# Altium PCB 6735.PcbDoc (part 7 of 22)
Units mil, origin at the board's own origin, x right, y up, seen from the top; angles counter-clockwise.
Board outline 2641.73 x 5165.35 mil, 6 copper layers (Top, Inner Layer 2, Inner Layer 3, Inner Layer 4, Inner Layer 5, Bottom), stack 35.7 mil thick; 1011 components, 790 nets, 4118 pads, 9325 vias.
Unrouted connection lines stored in the file: 4610.
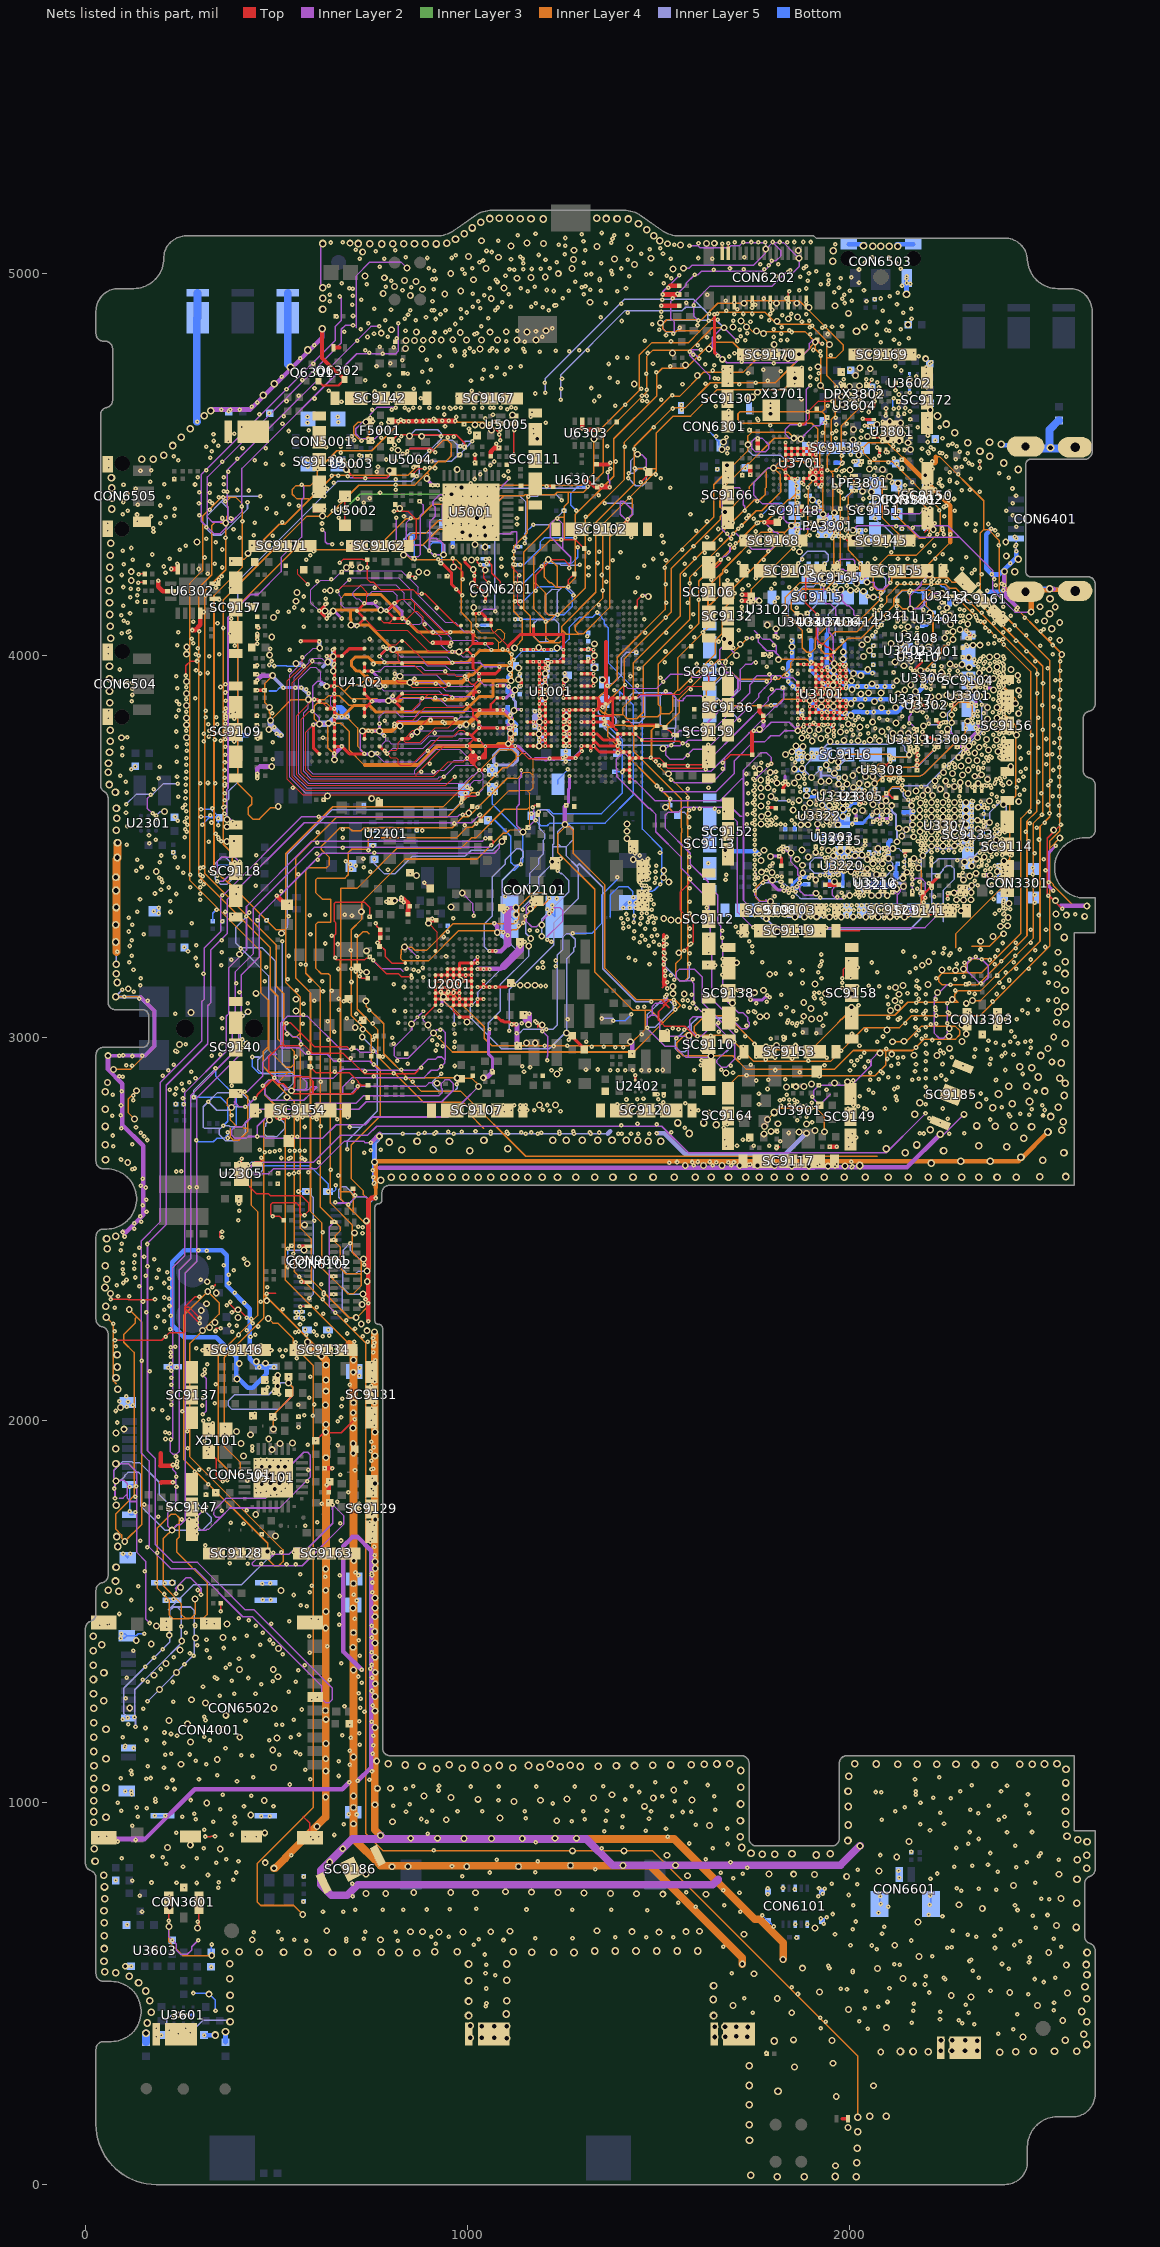
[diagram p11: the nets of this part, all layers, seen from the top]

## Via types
v1: diameter 12, hole 4, Top to Inner Layer 2, 3329 vias
v2: diameter 12, hole 4, Inner Layer 5 to Bottom, 3071 vias
v3: diameter 18, hole 10, Inner Layer 2 to Inner Layer 5, 1928 vias
v4: diameter 10, hole 4, Top to Inner Layer 2, 525 vias
v5: diameter 20, hole 12, Top to Bottom, 472 vias

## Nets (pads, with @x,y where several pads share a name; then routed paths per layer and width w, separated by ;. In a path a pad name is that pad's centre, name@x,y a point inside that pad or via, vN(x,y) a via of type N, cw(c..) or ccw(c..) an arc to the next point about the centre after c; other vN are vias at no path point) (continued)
D_GND: (continued)
  Top w4: DPX3802.5@2044.35,4707.8 DPX3802.5@2045.14,4707.8 ; DPX3802.5@2044.35,4707.8 DPX3802.5@2044.35,4709.22 ; DPX3802.5@2044.35,4709.22 2044.96,4708.14 DPX3802.5@2045.14,4707.8 ; DPX3802.5@2044.35,4709.22 v1(2043.31,4711.09) 2044.35,4710.05 DPX3802.5@2044.35,4709.22 ; U3308.2@2082.58,3700.59 U3308.7@2105.57,3723.58 ; U3801.4@2094.55,4633.33 v1@2094.55,4641.85 ; U3801.4@2094.55,4633.33 v1@2094.55,4641.85 ; DIPX3801.2@2125.6,4406.79 DIPX3801.2@2125.6,4406.09 DIPX3801.2@2125.6,4406.79 ; U3801.2@2126.8,4633.33 U3801.2@2126.05,4633.33 U3801.2@2126.8,4633.33 ; v1(2141.8,4633.33) 2141.67,4633.46 v1(2141.8,4633.33) ; U3801.15@2142.34,4538.84 U3801.15@2141.8,4538.85 U3801.15@2142.34,4538.84 ; U3801.17@2157.54,4570.83 2157.54,4570.34 U3801.17@2157.54,4570.83 ; U3801.20@2157.54,4618.33 U3801.20@2157.55,4617.59 U3801.20@2157.54,4618.33 ; DIPX3801.4@2159.06,4431.83 DIPX3801.4@2159.07,4431.68 DIPX3801.4@2159.06,4431.83 ; SC9150.3@2202.95,4330.72 SC9150.3@2202.59,4358.85 SC9150.3@2202.95,4330.72 ; v1@205.32,1545.49 205.89,1544.92 205.95,1544.86 v1(205.95,1544.99) 205.44,1545.49 v1@205.32,1545.49 ; C4115.2@465.61,3909.49 v1(465.95,3909.83) 468.61,3909.83 C4115.2@468.95,3909.49 C4115.2@465.61,3909.49 ; U5003.2@684.76,4502.42 v1(684.95,4502.23) U5003.2@684.76,4502.42 ; U5003.5@707.4,4502.42 v1(707.47,4502.49) U5003.5@707.4,4502.42 ; U4102.W13@828.35,3782.47 828.53,3782.65 U4102.W13@828.35,3782.47 ; v4(1029.98,3732.26) 1031.08,3732.11 1030.13,3732.11 v4(1029.98,3732.26) ; U1001.E3@1045.3,3700.34 v4(1045.72,3700.77) 1045.77,3700.69 U1001.E3@1045.3,3700.34 ; U5005.3@1120.26,4626.79 U5005.3@1121.31,4626.8 U5005.3@1120.26,4626.79 ; U2402.C2@1438.44,2889.84 1438.44,2891.96 U2402.C2@1438.44,2889.84 ; U3701.C4@1908.3,4526.9 1909.49,4526.9 1910.68,4526.9 v4(1910.68,4526.71) U3701.C4@1908.3,4526.9 ; LPF3801.3@2010.58,4431.4 v1(2011.31,4432.09) LPF3801.3@2010.58,4431.4 ; U3801.14@2126.05,4538.84 v1(2126.31,4539.09) U3801.14@2126.05,4538.85
  Top w5: U1001.C6@1011.72,3745.5 1014.23,3742.99 1019.73,3737.49 ; U1001.C6@1014.23,3748.01 1013.96,3747.74 1014.23,3747.47 1019.73,3741.97 ; 1019.73,3737.49 1019.73,3741.97 ; 1019.73,3737.49 1027,3730.22 1027.47,3729.75 v4(1029.98,3732.26) 1029.71,3732 1019.74,3741.97
  Top w6: Q6301.2@609.7,4717.85 620.56,4706.99 662.33,4706.99 677.2,4721.87 Q6302.2@677.2,4722.85 ; v4(998.48,3732.26) 1002.11,3735.89 1004.08,3737.86 ; 1010.36,3789.83 1010.36,3791.38 v4(1029.98,3811) ; U1001.C6@1013.96,3747.74 1011.72,3745.5 1008.74,3742.52 ; v4(1014.23,3999.98) U1001.B23@998.48,4015.73 ; 1014.62,3858.11 1014.08,3857.57 1014.08,3842.64 U1001.D11@1029.98,3826.75 ; 1017.36,3782.83 998.48,3763.95 v4(998.48,3763.76) ; 1018.96,3723.88 1018.89,3723.88 1013.84,3728.92 1013.28,3729.49 1012.72,3730.05 1006.88,3735.89 ; 1025.29,3730.22 1021.04,3730.22 1014.23,3737.03 1008.74,3742.52 ; 1060.74,3859.23 1060.74,3873.26 ; U1001.AC12@1329.19,3842.5 1379.56,3842.49 ; 1390.46,3804.49 1379.56,3815.39 1379.56,3842.49 ; U1001.AG15@1392.18,3889.74 1379.56,3889.74 1379.56,3842.49 ; v1(1438.31,2902.09) 1438.14,2901.92 1438.14,2889.54 U2402.C2@1438.44,2889.84 ; U3101.L11@1863.66,3851.35 U3101.L10@1863.66,3867.09 ; v4(1879.41,3819.85) v4(1895.16,3819.85) ; v1(1950.65,3622.59) 1962.26,3622.59 U3323.1@1962.78,3623.11 ; U3305.10@2012.15,3630.59 v1(2051.13,3630.59) ; U3305.2@2022.98,3613.86 U3305.3@2038.33,3613.86 ; v1(2095.65,3640.59) 2098.65,3640.59 2110.65,3628.59 L3342.2@2120.65,3628.59 ; U3306.7@2167.06,3960.28 2167.06,3962.16 2167.15,3962.16 2183.48,3978.49 2183.7,3978.49 2188.13,3982.92 U3410.1@2188.13,3987.72 ; v1(2193.65,3354.59) 2193.65,3366.48 2193.65,3377.27 2207.98,3391.59 v1(2214.65,3391.59) ; v4(998.48,3763.76) U1001.C6@1014.23,3748.01 ; v4(998.48,3763.76) U1001.C6@1014.23,3748.01 ; U1001.B23@998.48,4015.73 v4(1014.23,3999.98) U1001.B23@998.48,4015.73 ; 1004.08,3737.86 1004.91,3737.86 1006.88,3735.89 ; 1004.08,3737.86 1005.06,3738.84 ; 1005.06,3738.84 1006.88,3737.01 1006.88,3735.89 ; 1005.06,3738.84 1008.74,3742.52 ; 1008.74,3742.52 U1001.C6@1014.23,3748.01 ; 1060.74,3873.26 U1001.G15@1077.22,3889.74 1060.74,3873.26
  Top w7: v4(1863.66,3835.6) v4(1879.41,3835.6) U3101.J12@1895.16,3835.6 U3101.J11@1895.16,3851.35 ; U3101.L10@1863.66,3867.09 v4(1863.66,3882.84) ; v4(1863.66,3914.34) v4(1863.66,3898.59) ; U3101.L3@1863.66,3977.33 v4(1879.41,3977.33) ; U3101.K8@1879.41,3898.59 v4(1863.66,3898.59) ; v4(1895.16,3819.85) v4(1910.9,3819.85) v4(1926.65,3819.85) v4(1942.4,3819.85) v4(1958.15,3819.85) v4(1958.15,3804.1) v4(1958.15,3788.35) ; v4(1895.16,3898.59) U3101.J9@1895.16,3882.84 ; U3101.J4@1895.16,3961.58 U3101.H4@1910.9,3961.58 ; v4(1895.16,3977.33) U3101.H3@1910.9,3977.33 U3101.G3@1926.65,3977.33 v4(1926.65,3961.58) ; v4(1910.9,3867.09) U3101.H11@1910.9,3851.35 ; v4(1910.9,3898.59) v4(1910.9,3882.84) ; U3101.H6@1910.9,3930.09 U3101.G6@1926.65,3930.09 v4(1942.4,3930.09) ; U3101.G9@1926.65,3882.84 v4(1910.9,3882.84) ; U3101.G7@1926.65,3914.34 v4(1942.4,3914.34) ; U3101.G2@1926.65,3993.08 U3101.F2@1942.4,3993.08 ; v4(1942.4,3898.59) v4(1942.4,3882.84) U3101.E9@1958.15,3882.84 ; U3101.E10@1958.15,3867.09 U3101.E9@1958.15,3882.84 ; U3101.E6@1958.15,3930.09 v4(1942.4,3930.09) ; U3101.C11@1988.18,3851.35 U3101.D11@1973.9,3851.35 ; v4(1989.64,3835.6) U3101.D12@1973.9,3835.6 ; v4(1989.64,3851.35) v4(1989.64,3867.09) ; v4(1863.66,3882.84) v4(1863.66,3898.59) ; v4(1863.66,3882.84) v4(1879.41,3882.84) U3101.J9@1895.16,3882.84 ; U3101.J11@1895.16,3851.35 v4(1895.16,3867.09) U3101.J9@1895.16,3882.84 ; U3101.J11@1895.16,3851.35 U3101.H11@1910.9,3851.35 ; U3101.J9@1895.16,3882.84 v4(1910.9,3882.84) ; U3101.H11@1910.9,3851.35 v4(1926.65,3851.35) ; U3101.H4@1910.9,3961.58 U3101.H5@1910.9,3945.83 U3101.G5@1926.65,3945.83 ; U3101.H4@1910.9,3961.58 v4(1926.65,3961.58) ; v4(1926.65,3851.35) v4(1942.4,3851.35) ; v4(1926.65,3851.35) U3101.G10@1926.65,3867.09 v4(1942.4,3867.09) v4(1942.4,3851.35) ; U3101.G5@1926.65,3945.83 v4(1926.65,3961.58) ; U3101.G5@1926.65,3945.83 v4(1942.4,3945.83) v4(1942.4,3961.58) ; v4(1926.65,3961.58) v4(1942.4,3961.58) ; v4(1942.4,3851.35) v4(1942.4,3835.6) U3101.E12@1958.15,3835.6 ; v4(1942.4,3851.35) v4(1958.15,3851.35) ; v4(1942.4,3914.34) v4(1942.4,3930.09) ; v4(1942.4,3914.34) U3101.E7@1958.15,3914.34 ; v4(1942.4,3961.58) U3101.E4@1958.15,3961.58 ; U3101.E12@1958.15,3835.6 v4(1958.15,3851.35) ; U3101.E12@1958.15,3835.6 U3101.D12@1973.9,3835.6 ; v4(1958.15,3851.35) U3101.D11@1973.9,3851.35 ; U3101.E9@1958.15,3882.84 U3101.E8@1958.15,3898.59 ; U3101.E8@1958.15,3898.59 U3101.D8@1973.9,3898.59 ; U3101.E8@1958.15,3898.59 U3101.E7@1958.15,3914.34 ; U3101.E7@1958.15,3914.34 v4(1973.9,3914.34) ; U3101.E4@1958.15,3961.58 U3101.E3@1958.15,3977.33 v4(1973.9,3977.33) ; U3101.E4@1958.15,3961.58 v4(1973.9,3961.58) ; U3101.D12@1973.9,3835.6 U3101.D11@1973.9,3851.35 ; U3101.D11@1973.9,3851.35 U3101.D10@1973.9,3867.09 ; U3101.D10@1973.9,3867.09 U3101.D9@1973.9,3882.84 ; U3101.D10@1973.9,3867.09 v4(1989.64,3867.09) ; U3101.D9@1973.9,3882.84 U3101.D8@1973.9,3898.59 ; U3101.D9@1973.9,3882.84 v4(1989.64,3882.84) v4(1989.64,3867.09) ; U3101.D8@1973.9,3898.59 v4(1973.9,3914.34) ; v4(1973.9,3914.34) v4(1989.64,3914.34) v4(1989.64,3930.09) ; v4(1973.9,3914.34) v4(1973.9,3930.09) ; v4(1973.9,3930.09) v4(1989.64,3930.09) ; v4(1973.9,3930.09) v4(1973.9,3945.83) v4(1989.64,3945.83) ; v4(1973.9,3961.58) v4(1989.64,3961.58) ; v4(1973.9,3961.58) v4(1973.9,3977.33) ; v4(1973.9,3977.33) v4(1989.64,3977.33) v4(1989.64,3961.58) ; v4(1989.64,3930.09) v4(1989.64,3945.83) ; v4(1989.64,3945.83) v4(1989.64,3961.58)
  Top w8: v1(559.31,2424.09) v1@559.67,2423.73 ; v1(559.31,2455.09) v1@559.46,2455.23 ; v1(562.95,4037.49) v1@563.84,4038.37 ; v1(564.31,2362.09) v1@565.66,2360.74 ; v1(596.08,3819.11) 596.08,3758.83 U4102.AA2@611.82,3743.1 ; v1(598.95,3885.49) 607.6,3885.11 ; U4102.R3@631.5,3861.21 v1(651.18,3861.21) ; U4102.M3@631.5,3920.27 v1(651.18,3920.26) ; v1(631.5,4097.43) v1(611.81,4117.11) U4102.A3@631.5,4136.8 ; v1(651.18,3743.1) U4102.W4@651.19,3782.47 v1(651.18,3821.84) v1(651.18,3841.52) v1(651.18,3861.21) ; U4102.Y4@651.19,3762.79 v1(670.87,3762.78) 690.55,3743.1 v1(729.92,3743.1) ; U4102.G4@651.19,4018.69 U4102.H4@651.19,3999.01 ; U4102.B7@710.24,4117.12 v1(729.92,4136.8) U4102.B7@710.24,4117.12 ; U4102.W8@729.93,3782.47 U4102.V8@729.93,3802.16 v1(749.61,3802.15) ; U4102.T8@729.93,3841.53 U4102.R8@729.93,3861.21 v1(749.61,3880.89) U4102.N8@729.93,3900.58 U4102.M8@729.93,3920.27 ; U4102.J8@729.93,3979.32 U4102.K8@729.93,3959.64 v1(749.61,3959.63) ; U4102.G8@729.93,4018.69 729.45,4018.22 690.08,4018.22 U4102.H5@670.87,3999.01 U4102.H4@651.19,3999.01 ; U4102.Y10@769.3,3762.79 v1(788.98,3743.1) ; v1(769.29,3999) v1(788.98,4018.69) ; U4102.B11@788.98,4117.12 v1(808.66,4136.8) U4102.B11@788.98,4117.12 ; U4102.A12@810.9,4136.8 815.01,4140.91 816.01,4141.91 ; U4102.R13@828.35,3861.21 v1(808.66,3880.89) ; v1(828.35,4097.43) U4102.C12@808.67,4097.43 ; U4102.W13@828.53,3782.65 837.58,3782.65 845.63,3782.65 v1(854.08,3791.11) ; U2001.L12@915.58,3085.71 U2001.L11@915.58,3101.46 ; v1(930.95,4241.83) 932.92,4241.83 957.58,4217.17 957.58,4186.81 v1(986.3,4158.09) ; U2001.G10@978.38,3117.15 U2001.G10@978.31,3117.09 ; U2001.G14@978.57,3054.22 v4(1010.07,3054.22) ; 987.95,3164.49 v4(994.95,3164.49) v4(994.95,3164.49) ; v1(993.08,4254.11) 993.08,4244.11 1018.3,4218.89 1018.3,4189.11 1046.08,4161.33 U1001.E31@1046.08,4142.07 ; U1001.B9@998.48,3795.25 1004.94,3795.25 1010.36,3789.83 1017.36,3782.83 1021.08,3779.11 U1001.D8@1029.98,3779.11 ; U1001.B5@1002.31,3730.14 1002.31,3731.31 1003.25,3732.26 1006.88,3735.89 ; 1009.76,3720.98 1013.84,3716.89 1013.84,3718.77 1018.96,3723.88 1025.29,3730.22 1027,3730.22 1027.93,3730.22 1029.71,3732 v4(1029.98,3732.26) ; U1001.C15@1014.23,3889.74 1014.7,3890.21 1014.7,3900.73 1019.46,3905.48 v4(1029.98,3905.48) ; 1014.23,3968.48 v4(1014.23,3999.98) ; v4(1014.23,4062.97) 1014.23,4031.47 v4(1045.72,4031.47) ; 1014.62,3858.11 v4(1031.08,3858.11) 1048.08,3858.11 1048.22,3858.24 v4(1092.97,3858.25) ; v1(1019.08,4525.49) 1019.08,4515.36 L5010.2@1019.08,4505.83 ; U2001.D12@1025.82,3085.71 v4(1025.82,3101.46) v4(1041.57,3101.46) ; v4(1025.82,3132.96) v4(1041.57,3132.96) ; v4(1025.82,3180.2) v4(1041.57,3180.2) v4(1057.32,3180.2) ; v4(1025.82,3211.7) v4(1025.82,3195.95) U2001.E5@1010.07,3195.95 ; v4(1029.98,3700.77) v4(1045.72,3700.77) ; v4(1029.98,3952.73) v4(1029.98,3936.99) ; v4(1029.98,3779.51) U1001.D8@1029.98,3779.11 ; v4(1029.98,3811) U1001.H10@1092.97,3811 1093.07,3811.11 v4(1107.08,3811.11) 1110.95,3807.24 1110.95,3796.49 ; v4(1029.98,3952.73) 1055.91,3952.73 1056.01,3952.83 1072.95,3952.83 1082.95,3962.83 v4(1082.95,3970.49) ; v4(1041.57,3148.7) v4(1041.57,3132.96) ; v4(1045.72,4141.71) U1001.E31@1046.08,4142.07 ; v4(1045.72,4031.47) 1046.09,4031.83 1064.95,4031.83 ; U1001.E31@1046.08,4142.06 1045.76,4141.75 U1001.E31@1046.08,4142.07 ; v4(1057.32,3227.44) v4(1073.06,3227.44) ; U1001.F27@1061.47,4078.72 U1001.F28@1061.47,4094.47 U1001.E28@1045.72,4094.47 1046.08,4094.81 1046.08,4102.1 1037.98,4110.21 v4(1029.98,4110.21) ; U2001.A14@1073.06,3054.22 1078.15,3054.22 1082.73,3049.63 1082.73,3049.49 1087.39,3044.83 1091.71,3044.83 1094.71,3041.83 1108.95,3041.83 v1(1114.95,3035.83) ; U1001.G15@1077.22,3889.74 U1001.H15@1092.97,3889.74 ; U1001.G17@1077.22,3921.24 U1001.H17@1092.97,3921.24 ; v4(1104.95,4015.49) 1104.95,4023.07 1137.36,4055.49 1171.71,4055.49 ; C2011.2@1112.95,3143.83 1109.66,3140.54 1102.08,3132.96 v4(1073.06,3132.96) v4(1057.32,3132.96) v4(1041.57,3132.96) ; U1001.K9@1124.46,3795.25 1112.19,3795.25 1110.95,3796.49 ; v4(1140.21,3921.24) U1001.L18@1140.21,3936.99 ; v4(1140.21,4015.73) 1148.95,4015.72 ; U1001.M7@1155.96,3763.76 U1001.N7@1171.71,3763.76 U1001.P7@1187.46,3763.76 ; U1001.M9@1155.96,3795.25 U1001.N9@1171.71,3795.25 U1001.P9@1187.46,3795.25 ; U1001.M11@1155.96,3826.75 v4(1171.71,3826.75) U1001.P11@1187.46,3826.75 ; U1001.M21@1155.96,3984.23 v4(1171.71,3984.23) ; U1001.N27@1171.71,4078.72 1171.71,4055.49 ; 1209.02,4015.73 v4(1199.95,4015.73) 1182.95,4015.73 v4(1171.71,4015.73) 1161.78,4015.72 U1001.M23@1155.96,4015.73 ; 1209.03,4015.72 v4(1218.95,4015.73) ; v4(1214.29,3730.78) 1215.93,3732.42 v4(1249.04,3732.42) 1255.09,3732.42 1255.34,3732.17 v4(1282.48,3732.17) 1282.48,3734.02 v4(1298.95,3750.49) 1297.69,3750.84 v4(1297.69,3763.76) v4(1329.19,3763.76) ; U1001.T7@1218.95,3763.76 v4(1203.2,3763.76) ; U1001.V18@1250.45,3936.99 v4(1250.45,3921.24) U1001.V16@1250.45,3905.49 1250.45,3889.74 U1001.W15@1266.2,3889.74 U1001.Y15@1281.94,3889.74 U1001.AA15@1297.69,3889.74 U1001.AB15@1313.44,3889.74 U1001.AC15@1329.19,3889.74 1338.7,3889.74 1341.95,3886.49 1343.95,3879.49 ; C2055.2@1273.95,3005.49 1273.95,3005.09 1273.95,3002.99 1291.95,2984.99 1292.01,2984.99 1304.95,2972.05 C2058.2@1304.95,2969.49 ; v4(1297.69,3795.25) v4(1329.19,3795.25) ; v4(1297.69,3826.75) v4(1329.19,3826.75) ; U1001.AA17@1297.69,3921.24 U1001.AB17@1313.44,3921.24 v4(1329.19,3921.24) v4(1329.19,3952.73) U1001.AB19@1313.44,3952.73 U1001.AA19@1297.69,3952.73 ; U1001.AA21@1297.69,3984.23 U1001.AB21@1313.44,3984.23 v4(1329.19,3984.23) v4(1329.19,4015.73) U1001.AB23@1313.44,4015.73 U1001.AA23@1297.69,4015.73 ; U6301.B1@1302.7,4458.49 1313.95,4458.49 1330.95,4441.49 C6303.2@1338.95,4441.49 ; v4(1321.95,3751.49) 1321.95,3756.52 ; 1368.2,3826.75 v4(1329.19,3826.75) ; U1001.AH3@1407.93,3700.77 U1001.AJ3@1423.68,3700.77 ; U1001.AJ1@1423.68,3669.27 U1001.AJ2@1423.68,3685.02 U1001.AJ3@1423.68,3700.77 ; U1001.AK9@1439.43,3795.25 U1001.AJ9@1423.68,3795.25 U1001.AH9@1407.93,3795.25 U1001.AG9@1392.18,3795.25 U1001.AG8@1392.18,3779.51 ; U1001.AK15@1439.42,3889.74 v4(1423.68,3889.74) U1001.AH15@1407.93,3889.74 U1001.AG15@1392.18,3889.74 1376.43,3889.74 U1001.AE14@1360.69,3873.99 1347.45,3873.99 ; U1001.AL5@1455.17,3732.26 U1001.AK5@1439.43,3732.26 U1001.AJ5@1423.68,3732.26 ; 1512.95,3270.86 v1(1512.95,3255.11) v1(1512.95,3239.36) v1(1512.95,3223.62) v1(1512.95,3207.87) v1(1512.95,3192.12) 1512.95,3143.45 1512.95,3142.77 1512.95,3138.09 1516.31,3138.09 ; v1(1645.31,4893.09) 1645.31,4793.47 v1(1653.95,4784.83) ; v1(1785.65,3602.59) 1805.65,3602.59 C3228.1@1805.65,3600.59 ; v1(1815.65,3475.59) 1820.65,3470.59 C3250.1@1820.65,3450.59 ; C3226.1@1825.65,3645.59 1825.65,3655.59 1830.65,3660.59 v1(1830.65,3670.28) C3254.1@1830.65,3670.59 ; v4(1831.94,4558.21) U3701.H3@1831.94,4542.46 ; v4(1863.44,4463.72) U3701.G8@1847.69,4463.72 ; v4(1863.66,3914.34) U3101.L6@1863.66,3930.09 ; v4(1879.19,4447.97) U3701.E8@1879.19,4463.72 U3701.D8@1894.93,4463.72 ; v4(1879.41,3882.84) U3101.K8@1879.41,3898.59 ; U3101.K7@1879.41,3914.34 U3101.K8@1879.41,3898.59 ; v4(1879.41,3977.33) v4(1895.16,3977.33) ; v4(1895.16,3867.09) v4(1910.9,3867.09) ; C3259.2@1910.65,3500.59 v1(1910.65,3500.75) ; U3701.C4@1910.68,4526.9 1910.68,4534.63 ; v4(1910.68,4558.21) v4(1910.68,4542.46) ; v4(1910.9,3882.84) v4(1910.9,3867.09) ; U3101.H5@1910.9,3945.83 U3101.H6@1910.9,3930.09 U3101.H7@1910.9,3914.34 ; U3101.H4@1910.9,3961.58 U3101.H3@1910.9,3977.33 ; U3701.B8@1926.18,4463.97 U3701.B8@1926.06,4464.09 ; v4(1926.65,3851.35) v4(1926.65,3835.6) v4(1942.4,3835.6) ; U3101.G5@1926.65,3945.83 U3101.G6@1926.65,3930.09 U3101.G7@1926.65,3914.34 ; U3101.G3@1926.65,3977.33 U3101.G2@1926.65,3993.08 ; v4(1942.4,3914.34) v4(1942.4,3898.59) ; v4(1942.4,3930.09) v4(1942.4,3945.83) U3101.E5@1958.15,3945.83 ; v4(1958.15,3851.35) U3101.E10@1958.15,3867.09 ; U3101.E9@1958.15,3882.84 U3101.D9@1973.9,3882.84 ; U3101.E8@1958.15,3898.59 v4(1942.4,3898.59) ; U3101.E7@1958.15,3914.34 U3101.E6@1958.15,3930.09 ; U3101.E4@1958.15,3961.58 U3101.E5@1958.15,3945.83 ; U3101.D10@1973.9,3867.09 U3101.E10@1958.15,3867.09 ; v4(1973.9,3930.09) U3101.E6@1958.15,3930.09 ; v4(1973.9,3961.58) v4(1973.9,3945.83) U3101.E5@1958.15,3945.83 ; v1(1980.54,4215.67) v1@1980.65,4215.59 ; v1@2028.31,4570.34 v1(2029.08,4570.11) ; v1(2033.31,4620.09) 2043.08,4618.11 U3801.6@2062.53,4618.11 ; v1(2039.08,4602.11) U3801.7@2063.06,4602.11 ; v1(2077.08,4523.11) U3801.11@2077.08,4537.12 ; v1(2093.31,4532.94) v1@2094.55,4532.94 ; v1(2144.65,3476.59) 2144.65,3489.45 U3307.38@2149.27,3489.45 ; v1(2160.65,3855.59) 2168.13,3863.07 U3317.1@2168.13,3877.72 ; v1(2175.65,3700.59) v1(2175.65,3713.59) v1(2175.65,3726.59) 2175.65,3754.75 v1(2177.48,3756.58) ; v1(2184.9,3886.34) v1(2184.9,3870.59) U3302.9@2200.65,3870.59 ; v1(2189.6,3800.4) 2188.5,3799.3 2201.43,3786.37 L3330.2@2201.43,3785.59 ; L3330.2@2200.65,3785.59 L3330.2@2201.43,3785.59 ; v1(2206.65,3404.59) 2214.34,3404.59 C3340.1@2231.51,3421.76 ; C3312.2@2225.65,3830.59 2230.65,3825.59 v1(2250.65,3825.59) ; C3340.1@2229.82,3421.76 C3340.1@2231.51,3421.76 ; U3309.5@2230.06,3760.9 U3309.4@2230.06,3780.59 2217.65,3780.59 2212.65,3785.59 L3330.2@2201.43,3785.59 ; U3401.6@2230.65,3994.84 U3401.6@2230.8,3994.99 ; U3401.9@2230.65,4010.59 2230.84,4010.59 2230.84,3994.99 v1(2232.28,3994.99) ; C3340.1@2231.65,3423.59 2231.65,3421.76 C3340.1@2231.51,3421.76 ; v1(2255.65,3363.59) 2255.79,3363.59 2255.79,3378.46 v1(2255.92,3378.46) ; v1(2265.65,3870.59) L3302.2@2268.67,3870.59 ; v1(2350.37,3564.64) 2350.77,3565.04 U3307.16@2352.03,3565.04 ; v1@559.46,2455.23 CON6102.5@582.62,2455.23 v1@559.46,2455.23 ; v1@559.67,2423.73 CON6102.7@582.62,2423.74 v1@559.67,2423.73 ; v1@563.84,4038.37 U4102.F2@611.82,4038.38 v1@563.84,4038.37 ; v1@565.66,2360.74 582.62,2360.74 v1@565.66,2360.74 ; 607.6,3885.11 U4102.P2@611.82,3880.9 607.6,3885.11 ; v1(651.18,3861.21) v1(651.18,3900.58) v1(651.18,3920.26) ; v1(651.18,3920.26) v1(651.18,3939.95) ; v1(651.18,3920.26) v1(651.18,3939.95) ; v1(651.18,3939.95) U4102.K4@651.19,3959.64 ; v1(651.18,3939.95) U4102.K4@651.19,3959.64 ; U4102.K4@651.19,3959.64 v1(651.18,3979.32) ; U4102.K4@651.19,3959.64 v1(651.18,3979.32) ; v1(651.18,3979.32) U4102.H4@651.19,3999.01 ; v1(651.18,3979.32) U4102.H4@651.19,3999.01 ; U4102.H4@651.19,3999.01 v1(631.5,3999) U4102.H4@651.19,3999.01 ; U4102.B7@710.24,4117.12 U4102.C8@729.93,4097.43 ; U4102.B7@710.24,4117.12 U4102.C8@729.93,4097.43 ; U4102.C8@729.93,4097.43 v1(710.24,4077.74) U4102.C8@729.93,4097.43 ; U4102.B11@788.98,4117.12 U4102.C12@808.67,4097.43 ; U4102.B11@788.98,4117.12 U4102.C12@808.67,4097.43 ; U4102.B11@788.98,4117.12 U4102.C12@808.67,4097.43 ; v1(808.66,3880.89) U4102.N13@828.35,3900.58 v1(808.66,3880.89) ; U2001.L11@915.58,3101.46 U2001.K11@931.33,3101.46 ; U2001.L11@915.58,3101.46 U2001.K11@931.33,3101.46 ; U2001.L11@915.58,3101.46 U2001.L10@915.58,3117.21 ; U2001.L10@915.58,3117.21 U2001.K10@931.33,3117.21 ; U2001.L10@915.58,3117.21 U2001.L9@915.58,3128.61 ; U2001.L10@915.58,3117.21 U2001.K10@931.33,3117.21 ; U2001.L10@915.58,3117.21 v4(915.58,3132.96) ; U2001.L10@915.58,3117.21 U2001.L9@915.58,3128.61 ; U2001.L10@915.58,3117.21 v4(915.58,3132.96) ; U2001.L10@915.58,3117.21 U2001.K10@931.33,3117.21 ; U2001.L9@915.58,3128.61 v4(915.58,3132.96) ; U2001.L9@915.58,3128.61 v4(915.58,3132.96) ; v4(915.58,3132.96) U2001.L8@915.58,3148.7 ; v4(915.58,3132.96) v4(931.33,3132.96) ; v4(915.58,3132.96) U2001.L9@915.58,3135.09 ; v4(915.58,3132.96) U2001.L9@915.58,3135.09 ; U2001.L9@915.58,3135.09 U2001.L8@915.58,3148.7 ; U2001.L8@915.58,3148.7 U2001.L7@915.58,3164.45 ; U2001.L8@915.58,3148.7 U2001.K8@931.33,3148.7 ; U2001.L8@915.58,3148.7 U2001.L7@915.58,3164.45 ; U2001.L8@915.58,3148.7 U2001.K8@931.33,3148.7 ; U2001.L7@915.58,3164.45 U2001.K7@931.33,3164.45 ; U2001.K11@931.33,3101.46 U2001.J11@947.08,3101.46 ; U2001.K11@931.33,3101.46 U2001.J11@947.08,3101.46 ; U2001.K11@931.33,3101.46 U2001.K10@931.33,3117.21 ; U2001.K11@931.33,3101.46 U2001.K10@931.33,3117.21 ; U2001.K11@931.33,3101.46 U2001.J11@944.45,3101.46 ; U2001.K11@931.33,3101.46 U2001.J11@944.45,3101.46 ; U2001.K11@931.33,3101.46 U2001.J11@947.08,3101.46 ; U2001.K10@931.33,3117.21 U2001.K9@931.33,3132.02 ; U2001.K10@931.33,3117.21 U2001.K9@931.33,3132.02 ; U2001.K10@931.33,3117.21 U2001.J10@947.08,3117.21 ; U2001.K9@931.33,3132.02 v4(931.33,3132.96) ; U2001.K9@931.33,3132.02 947.08,3132.02 U2001.J9@947.2,3132.02 ; v4(931.33,3132.96) U2001.K8@931.33,3148.7 ; U2001.K8@931.33,3148.7 U2001.J8@947.08,3148.7 ; U2001.K8@931.33,3148.7 U2001.J8@947.08,3148.7 ; U2001.K8@931.33,3148.7 U2001.K7@931.33,3164.45 ; U2001.K8@931.33,3148.7 U2001.J8@947.08,3148.7 ; U2001.K8@931.33,3148.7 U2001.K7@931.33,3164.45 ; U2001.K8@931.33,3148.7 U2001.K7@931.33,3164.45 ; U2001.K7@931.33,3164.45 U2001.J7@947.08,3164.45 ; U2001.J11@944.45,3101.46 U2001.J11@947.08,3101.46 ; U2001.J11@947.08,3101.46 U2001.J10@947.08,3115.85 ; U2001.J11@947.08,3101.46 U2001.H11@962.83,3101.46 ; U2001.J11@947.08,3101.46 960.86,3101.46 U2001.H11@962.83,3101.46 ; U2001.J11@947.08,3101.46 U2001.H11@962.83,3101.46 ; U2001.J10@947.08,3115.85 947.31,3116.09 U2001.J10@947.31,3117.21 ; U2001.J10@947.08,3115.85 U2001.J10@947.08,3117.21 ; U2001.J10@947.08,3117.21 U2001.J10@947.31,3117.21 ; U2001.J9@947.09,3132.9 U2001.J9@947.14,3132.72 ; U2001.J9@947.1,3132.89 U2001.J9@947.2,3132.46 ; U2001.J9@947.1,3132.89 U2001.J9@947.2,3132.3 ; U2001.J9@947.09,3132.9 v4(947.08,3132.96) ; v4(947.08,3132.96) 947.15,3132.89 U2001.J9@947.2,3132.84 ; U2001.J9@947.09,3132.92 U2001.J9@947.2,3132.02 ; v4(947.08,3132.96) U2001.J9@947.2,3132.49 ; v4(947.08,3132.96) U2001.J9@947.2,3132.02 ; U2001.J9@947.09,3132.92 U2001.J9@947.2,3132.02 ; v4(947.08,3132.96) U2001.J9@947.14,3132.72 ; v4(947.08,3132.96) U2001.J9@947.2,3132.84 ; U2001.J8@947.08,3148.4 947.08,3147.18 U2001.J8@947.2,3147.06 ; U2001.J8@947.08,3148.4 U2001.J8@947.08,3148.7 ; U2001.J8@947.08,3148.4 U2001.J8@947.08,3148.7 ; U2001.J8@947.08,3148.7 U2001.J8@947.2,3148.7 ; U2001.J8@947.08,3148.7 U2001.J8@947.2,3148.4 ; U2001.J8@947.08,3148.7 U2001.J8@947.2,3148.4 ; U2001.J8@947.08,3148.7 U2001.J8@947.2,3148.7 ; U2001.J8@947.08,3148.7 U2001.J7@947.08,3164.45 ; U2001.J8@947.08,3148.7 U2001.J7@947.08,3164.45 ; U2001.J8@947.08,3148.7 U2001.J7@947.08,3164.45 ; U2001.J7@947.08,3164.45 U2001.H7@962.83,3164.45 ; U2001.J7@947.08,3164.45 U2001.J6@947.08,3180.2 ; U2001.J7@947.08,3164.45 U2001.H7@962.83,3164.45 ; U2001.J7@947.08,3164.45 U2001.J6@947.08,3180.2 ; U2001.J7@947.08,3164.45 U2001.H7@962.83,3164.45 ; U2001.J6@947.08,3180.2 U2001.H6@962.83,3180.2 ; U2001.J9@947.14,3132.72 947.16,3132.65 U2001.J9@947.2,3132.49 ; U2001.J9@947.14,3132.72 947.17,3132.59 U2001.J9@947.2,3132.47 ; U2001.J9@947.2,3131.97 U2001.J9@947.31,3131.09 ; U2001.J9@947.2,3131.97 U2001.J9@947.2,3132.02 ; U2001.J9@947.2,3131.98 U2001.J9@947.31,3131.09 ; U2001.J9@947.2,3131.97 947.2,3131.09 U2001.J9@947.31,3131.09 ; U2001.J9@947.2,3132.02 U2001.J9@947.2,3132.3 ; U2001.J9@947.2,3132.3 U2001.J9@947.2,3132.46 ; U2001.J9@947.2,3132.3 U2001.J9@947.25,3132.02 ; U2001.J9@947.2,3132.46 U2001.J9@947.23,3132.33 ; U2001.J9@947.2,3132.49 U2001.J9@947.2,3132.83 ; U2001.J9@947.2,3132.47 U2001.J9@947.23,3132.34 ; U2001.J9@947.2,3132.84 U2001.J8@947.2,3147.06 ; U2001.J8@947.2,3147.06 U2001.J8@947.2,3148.4 ; U2001.J8@947.2,3148.4 U2001.J8@947.2,3148.7 ; U2001.J8@947.2,3148.7 v4(962.83,3148.7) ; U2001.J8@947.2,3148.7 v4(962.83,3148.7) ; U2001.J9@947.25,3132.02 U2001.J9@947.31,3131.09 ; U2001.J9@947.25,3132.02 U2001.J9@947.31,3132.02 ; U2001.J9@947.23,3132.33 U2001.J9@947.31,3132.02 ; U2001.J9@947.23,3132.34 U2001.J9@947.31,3132.02 ; U2001.J10@947.31,3117.21 U2001.J9@947.31,3131.09 ; U2001.J10@947.31,3117.21 v4(962.83,3117.21) ; U2001.J9@947.31,3131.09 U2001.J9@947.31,3132.02 ; U2001.J9@947.31,3132.02 U2001.H9@962.82,3132.02 ; U2001.H12@962.83,3085.71 U2001.G12@978.57,3085.71 ; U2001.H12@962.83,3085.71 U2001.H11@962.83,3101.46 ; U2001.H12@962.83,3085.71 U2001.H11@962.83,3101.46 ; U2001.H11@962.83,3101.46 v4(962.83,3117.21) ; U2001.H11@962.83,3101.46 970.7,3101.46 ; U2001.H11@962.83,3101.46 v4(978.57,3101.46) ; U2001.H11@962.83,3101.46 v4(978.57,3101.46) ; U2001.H11@962.83,3101.46 970.7,3101.46 ; U2001.H11@962.83,3101.46 v4(978.57,3101.46) ; v4(962.83,3117.21) v4(962.83,3117.21) ; v4(962.83,3117.21) v4(962.83,3117.21) ; v4(962.83,3117.21) U2001.G10@978.31,3117.15 ; v4(962.83,3117.21) U2001.H9@962.82,3132.02 ; v4(962.83,3117.21) U2001.G10@978.31,3117.21 ; v4(962.83,3117.21) U2001.G10@978.31,3117.21 ; v4(962.83,3117.21) U2001.G10@978.31,3117.21 ; U2001.H9@962.82,3132.02 U2001.H9@962.83,3132.96 ; U2001.H9@962.82,3132.02 U2001.H9@962.83,3132.96 ; U2001.H9@962.83,3132.02 U2001.G9@978.31,3132.02 ; U2001.H9@962.83,3132.96 U2001.H9@962.83,3132.96 ; U2001.H9@962.83,3132.96 U2001.H9@962.83,3132.96 ; U2001.H9@962.83,3132.96 962.89,3133.02 U2001.H9@962.83,3132.96 ; U2001.H9@962.83,3132.96 v4(962.83,3148.7) ; v4(962.83,3148.7) U2001.H7@962.83,3164.45 ; v4(962.83,3148.7) U2001.G8@978.44,3148.7 ; U2001.H7@962.83,3164.45 U2001.H6@962.83,3180.2 ; U2001.H7@962.83,3164.45 U2001.G7@978.57,3164.45 ; U2001.H7@962.83,3164.45 U2001.H6@962.83,3180.2 ; U2001.H7@962.83,3164.45 U2001.H6@962.83,3180.2 ; U2001.H7@962.83,3164.45 U2001.G7@978.57,3164.45 ; U2001.H7@962.83,3164.45 U2001.G7@978.57,3164.45 ; U2001.H6@962.83,3180.2 U2001.G6@978.57,3180.2 ; 970.7,3101.46 v4(978.57,3101.46) ; 970.7,3101.46 v4(978.57,3101.46) ; U2001.G10@978.31,3117.09 U2001.G10@978.57,3117.09 ; U2001.G10@978.31,3117.09 U2001.G10@978.31,3117.15 ; U2001.G10@978.31,3117.09 v4(978.57,3117.21) ; U2001.G10@978.31,3117.09 v4(978.57,3117.21) ; U2001.G10@978.31,3117.15 U2001.G10@978.31,3117.21 ; U2001.G10@978.31,3117.15 U2001.G10@978.39,3117.17 ; U2001.G10@978.31,3117.15 U2001.G10@978.39,3117.17 ; U2001.G10@978.31,3117.21 U2001.G9@978.31,3132.02 ; U2001.G10@978.31,3117.21 U2001.G10@978.44,3117.21 ; U2001.G10@978.32,3117.21 U2001.G10@978.44,3117.21 ; U2001.G10@978.31,3117.21 U2001.G10@978.44,3117.21 ; U2001.G10@978.32,3117.21 U2001.G10@978.44,3117.21 ; U2001.G9@978.31,3132.02 U2001.G9@978.57,3132.02 ; U2001.G9@978.31,3132.02 U2001.G9@978.31,3133.02 ; U2001.G9@978.31,3133.02 U2001.G9@978.31,3133.09 ; U2001.G9@978.31,3133.02 U2001.G9@978.57,3132.96 ; U2001.G9@978.31,3133.09 U2001.G9@978.44,3133.09 ; U2001.G9@978.31,3133.09 U2001.G9@978.57,3132.96 ; U2001.G10@978.39,3117.17 U2001.G10@978.44,3117.21 ; U2001.G10@978.39,3117.17 U2001.G10@978.46,3117.18 ; U2001.G10@978.39,3117.17 v4(978.57,3117.21) ; U2001.G10@978.39,3117.17 v4(978.57,3117.21) ; U2001.G10@978.39,3117.17 U2001.G10@978.46,3117.18 ; U2001.G10@978.44,3117.21 v4(978.57,3117.21) ; U2001.G10@978.44,3117.21 v4(978.57,3117.21) ; U2001.G10@978.46,3117.18 v4(978.57,3117.21) ; U2001.G10@978.46,3117.18 v4(978.57,3117.21) ; U2001.G10@978.44,3117.21 v4(978.57,3117.21) ; U2001.G9@978.44,3133.09 U2001.G9@978.57,3132.96 ; U2001.G9@978.44,3133.09 U2001.G8@978.44,3148.4 ; U2001.G9@978.44,3133.09 U2001.G9@978.57,3132.96 ; U2001.G8@978.44,3148.4 978.66,3148.61 U2001.G8@978.57,3148.7 ; U2001.G8@978.44,3148.4 U2001.G8@978.44,3148.7 ; U2001.G8@978.44,3148.7 U2001.G8@978.57,3148.7 ; U2001.G12@978.57,3085.71 U2001.F12@994.32,3085.71 ; U2001.G12@978.57,3085.71 v4(978.57,3101.46) ; U2001.G12@978.57,3085.71 v4(978.57,3101.46) ; U2001.G12@978.57,3085.71 v4(978.57,3101.46) ; v4(978.57,3101.46) U2001.G10@978.57,3117.09 ; v4(978.57,3101.46) U2001.F11@994.32,3101.46 ; v4(978.57,3101.46) U2001.G10@978.57,3117.09 ; v4(978.57,3101.46) 983.82,3101.46 ; v4(978.57,3101.46) U2001.F11@994.32,3101.46 ; U2001.G10@978.57,3117.09 v4(978.57,3117.21) ; U2001.G10@978.57,3117.09 v4(978.57,3117.21) ; U2001.G10@978.57,3117.09 v4(978.57,3117.21) ; v4(978.57,3117.21) U2001.G9@978.57,3132.02 ; v4(978.57,3117.21) U2001.G9@978.57,3132.02 ; U2001.G9@978.57,3132.02 U2001.G9@978.57,3132.96 ; U2001.G9@978.57,3132.02 U2001.G9@978.57,3132.96 ; U2001.G8@978.57,3148.7 993.95,3148.7 ; U2001.G8@978.57,3148.7 U2001.G7@978.57,3164.45 ; U2001.G8@978.57,3148.7 U2001.G7@978.57,3164.45 ; U2001.G8@978.57,3148.7 U2001.G7@978.57,3164.45 ; U2001.G7@978.57,3164.45 987.95,3164.45 v4(994.95,3164.49) ; U2001.G7@978.57,3164.45 U2001.G6@978.57,3180.2 ; U2001.G7@978.57,3164.45 U2001.G6@978.57,3180.2 ; U2001.G6@978.57,3180.2 978.57,3195.45 ; U2001.G6@978.57,3180.2 v4@992.95,3180.2 ; U2001.G6@978.57,3180.2 v4@992.95,3180.2 ; U2001.G6@978.57,3180.2 978.57,3195.45 ; 978.57,3195.45 979.07,3195.95 ; 979.07,3195.95 U2001.E5@1010.07,3195.95 ; 979.07,3195.95 U2001.E5@1010.07,3195.95 ; 983.82,3101.46 U2001.F11@994.32,3101.46 ; 983.82,3101.46 U2001.F11@994.32,3101.46 ; v4@992.95,3180.2 v4(992.95,3180.49) 993.24,3180.49 v4@992.95,3180.2 ; v4@992.95,3180.2 U2001.E6@1010.07,3180.2 ; 993.95,3148.7 993.95,3163.49 v4(994.95,3164.49) ; 993.95,3148.7 U2001.E8@1010.07,3148.7 ; U2001.F12@994.32,3085.71 U2001.F11@994.32,3101.46 ; U2001.F12@994.32,3085.71 v4(1010.07,3085.71) ; U2001.F12@994.32,3085.71 U2001.F11@994.32,3101.46 ; U2001.F12@994.32,3085.71 U2001.F11@994.32,3101.46 ; U2001.F11@994.32,3101.46 U2001.E11@1010.07,3101.46 ; U2001.F11@994.32,3101.46 U2001.E11@1010.07,3101.46 ; U2001.F11@994.32,3101.46 U2001.E11@1010.07,3101.46 ; v4(994.95,3164.49) U2001.E7@1009.95,3164.45 ; U2001.E7@1009.95,3164.45 v4(1010.07,3164.45) ; U2001.E7@1009.95,3164.45 v4(1010.07,3164.45) ; v4(1010.07,3085.71) U2001.E11@1010.07,3101.46 ; v4(1010.07,3085.71) U2001.E11@1010.07,3101.46 ; U2001.E11@1010.07,3101.46 U2001.E10@1010.07,3117.21 ; U2001.E11@1010.07,3101.46 U2001.E10@1010.07,3117.21 ; U2001.E10@1010.07,3117.21 U2001.E9@1010.07,3132.96 ; U2001.E10@1010.07,3117.21 U2001.E9@1010.07,3132.96 ; U2001.E9@1010.07,3132.96 U2001.E8@1010.07,3148.7 ; U2001.E9@1010.07,3132.96 U2001.E8@1010.07,3148.7 ; U2001.E9@1010.07,3132.96 U2001.E8@1010.07,3148.7 ; U2001.E8@1010.07,3148.7 v4(1010.07,3164.45) ; U2001.E8@1010.07,3148.7 v4(1010.07,3164.45) ; v4(1010.07,3164.45) U2001.E7@1010.07,3164.97 ; v4(1010.07,3164.45) U2001.E7@1010.07,3164.97 ; U2001.E7@1010.07,3164.97 U2001.E6@1010.07,3180.2 ; U2001.E7@1010.07,3164.97 U2001.E6@1010.07,3180.2 ; U2001.E6@1010.07,3180.2 U2001.E5@1010.07,3195.95 ; L5010.2@1019.08,4505.7 1019.08,4505.61 1019.08,4504.11 1019.95,4504.11 L5010.2@1020.08,4504.11 ; L5010.2@1019.08,4505.7 L5010.2@1019.95,4504.32 ; L5010.2@1019.08,4505.7 L5010.2@1019.08,4505.83 ; L5010.2@1019.08,4505.83 1019.26,4505.52 L5010.2@1019.95,4504.33 ; L5010.2@1019.95,4504.33 L5010.2@1020.08,4504.11 ; L5010.2@1019.95,4504.32 L5010.2@1020.08,4504.11 ; v4(1029.98,4110.21) U1001.C29@1014.23,4110.21 v4(1029.98,4110.21) ; v4(1029.98,3732.26) U1001.D5@1031.08,3732.11 ; v4(1029.98,3732.26) U1001.D5@1031.08,3732.11 ; v4(1029.98,3732.26) U1001.D5@1031.08,3732.11 ; v4(1029.98,3732.26) U1001.D5@1030.93,3732.26 ; U1001.D8@1029.98,3779.11 v4(1029.98,3779.51) U1001.D8@1029.98,3779.11 ; U1001.D5@1030.93,3732.26 U1001.D5@1031.08,3732.11 ; U1001.D5@1030.93,3732.26 U1001.D5@1032.61,3732.26 ; U1001.D5@1032.61,3732.26 1046.08,3745.73 ; U1001.D5@1032.61,3732.26 1046.08,3732.26 1046.08,3745.73 ; 1046.08,3745.73 v4(1046.08,3763.11) 1110.95,3763.11 ; 1110.95,3763.11 1110.95,3796.49 ; 1110.95,3763.11 U1001.K7@1123.81,3763.11 ; U1001.K7@1123.81,3763.11 v4(1124.46,3763.76) U1001.K7@1123.81,3763.11 ; 1148.95,4015.72 U1001.M23@1155.96,4015.73 ; 1148.95,4015.72 U1001.M23@1155.96,4015.73 ; v4(1171.71,3984.23) v4(1187.46,3984.23) ; v4(1171.71,3984.23) v4(1187.46,3984.23) ; 1171.71,4055.49 1249.95,4055.49 1250.45,4054.99 1250.45,4015.73 U1001.V22@1250.45,3999.98 U1001.V21@1250.45,3984.23 U1001.U21@1234.7,3984.23 v4(1218.95,3984.23) v4(1203.2,3984.23) ; U1001.P7@1187.46,3763.76 v4(1187.46,3779.51) ; U1001.P7@1187.46,3763.76 v4(1203.2,3763.76) ; v4(1187.46,3779.51) v4(1203.2,3779.51) ; v4(1187.46,3779.51) U1001.P9@1187.46,3795.25 ; U1001.P9@1187.46,3795.25 v4(1187.46,3811) ; U1001.P9@1187.46,3795.25 v4(1203.2,3795.25) ; v4(1187.46,3811) U1001.P11@1187.46,3826.75 ; v4(1187.46,3811) 1187.95,3810.74 U1001.R10@1203.2,3810.74 ; U1001.P11@1187.46,3826.75 U1001.P12@1187.46,3842.5 ; U1001.P11@1187.46,3826.75 v4(1203.2,3826.75) ; U1001.P12@1187.46,3842.5 U1001.R12@1203.2,3842.5 ; U1001.P12@1187.46,3842.5 U1001.P13@1187.46,3858.25 ; U1001.P13@1187.46,3858.25 U1001.R13@1203.2,3858.25 ; U1001.P13@1187.46,3858.25 v4(1187.46,3873.99) ; U1001.P13@1187.46,3858.25 U1001.P15@1187.45,3889.74 ; U1001.P13@1187.46,3858.25 U1001.R13@1203.2,3858.25 ; U1001.P13@1187.46,3858.25 U1001.R13@1203.2,3858.25 ; v4(1187.46,3873.99) v4(1203.2,3873.99) ; v4(1187.46,3873.99) U1001.P15@1187.45,3889.74 ; U1001.P15@1187.46,3889.74 U1001.R15@1203.2,3889.74 ; v4(1187.46,3889.74) U1001.P17@1187.46,3921.24 ; v4(1187.46,3889.74) v4(1187.46,3905.49) ; v4(1187.46,3905.49) U1001.P17@1187.46,3921.24 ; v4(1187.46,3905.49) v4(1203.2,3905.49) ; U1001.P17@1187.46,3921.24 U1001.R17@1203.2,3921.24 ; U1001.P17@1187.46,3921.24 v4(1187.46,3952.73) ; U1001.P17@1187.46,3921.24 U1001.R17@1203.2,3921.24 ; U1001.P17@1187.46,3921.24 v4(1187.46,3936.99) ; U1001.P17@1187.46,3921.24 U1001.R17@1203.2,3921.24 ; v4(1187.46,3936.99) v4(1203.2,3936.99) ; v4(1187.46,3936.99) v4(1187.46,3952.73) ; v4(1187.46,3952.73) U1001.R19@1203.2,3952.73 ; v4(1187.46,3952.73) v4(1187.46,3968.48) ; v4(1187.46,3952.73) U1001.R19@1203.2,3952.73 ; v4(1187.46,3968.48) v4(1203.2,3968.48) ; v4(1187.46,3968.48) v4(1187.46,3984.23) ; v4(1187.46,3984.23) v4(1203.2,3984.23) ; v4(1203.2,3763.76) v4(1203.2,3779.51) ; v4(1203.2,3779.51) v4(1203.2,3795.25) ; v4(1203.2,3795.25) U1001.T9@1218.95,3795.25 v4(1203.2,3795.25) ; v4(1203.2,3795.25) U1001.R10@1203.2,3810.74 ; U1001.R10@1203.2,3810.74 v4(1203.2,3811) v4(1203.2,3826.75) ; v4(1203.2,3826.75) U1001.T11@1218.95,3826.75 v4(1203.2,3826.75) ; v4(1203.2,3826.75) U1001.R12@1203.2,3842.5 ; U1001.R12@1203.2,3842.5 U1001.R13@1203.2,3858.25 ; U1001.R13@1203.2,3858.25 v4(1203.2,3873.99) ; U1001.R13@1203.2,3858.25 v4(1203.2,3873.99) ; v4(1203.2,3873.99) U1001.R15@1203.2,3889.74 ; v4(1203.2,3873.99) U1001.R15@1203.2,3889.74 ; U1001.R15@1203.2,3889.74 v4(1203.2,3905.49) ; v4(1203.2,3905.49) U1001.R17@1203.2,3921.24 ; U1001.R17@1203.2,3921.24 v4(1203.2,3936.99) ; v4(1203.2,3936.99) U1001.R19@1203.2,3952.73 ; U1001.R19@1203.2,3952.73 v4(1203.2,3968.48) ; U1001.R19@1203.2,3952.73 v4(1203.2,3968.48) ; v4(1203.2,3968.48) v4(1203.2,3984.23) ; U1001.V8@1250.45,3779.51 U1001.V7@1250.45,3763.76 v4(1266.2,3763.76) U1001.W8@1266.2,3779.51 ; U1001.V8@1250.45,3779.51 v4(1250.45,3795.25) ; U1001.V8@1250.45,3779.51 U1001.W8@1266.2,3779.51 ; U1001.V9@1250.45,3795.25 v4(1266.2,3795.25) ; v4(1250.45,3795.25) U1001.V10@1250.45,3811 ; U1001.V10@1250.45,3811 v4(1250.45,3826.75) ; U1001.V10@1250.45,3811 U1001.W10@1266.2,3811 ; U1001.V11@1250.45,3826.75 v4(1266.2,3826.75) ; v4(1250.45,3826.75) U1001.V12@1250.45,3842.5 ; U1001.V12@1250.45,3842.5 1250.45,3858.24 v4(1266.2,3858.25) ; U1001.V12@1250.45,3842.5 U1001.W12@1266.2,3842.5 ; U1001.W8@1266.2,3779.51 v4(1266.2,3795.25) ; v4(1266.2,3795.25) U1001.W10@1266.2,3811 ; U1001.W10@1266.2,3811 v4(1266.2,3826.75) ; v4(1266.2,3826.75) U1001.W12@1266.2,3842.5 ; U1001.W12@1266.2,3842.5 v4(1266.2,3858.25) ; U1001.W12@1266.2,3842.5 v4(1266.2,3858.25) ; v4(1266.2,3858.25) U1001.AA13@1297.69,3858.25 v4(1329.19,3858.25) ; 1321.95,3756.52 v4(1329.19,3763.76) ; 1321.95,3756.52 v4(1329.19,3763.76) ; v4(1329.19,3763.76) 1344.93,3748.01 ; v4(1329.19,3763.76) U1001.AC8@1329.19,3779.51 ; U1001.AC8@1329.19,3779.51 1344.93,3763.75 v4(1392.18,3763.76) ; U1001.AC8@1329.19,3779.51 v4(1329.19,3795.25) ; v4(1329.19,3795.25) 1339.18,3795.25 1354.93,3779.5 U1001.AG8@1392.18,3779.51 ; v4(1329.19,3795.25) v4(1329.19,3826.75) ; v4(1329.19,3826.75) U1001.AC12@1329.19,3842.5 v4(1329.19,3858.25) ; v4(1329.19,3858.25) 1337.95,3858.49 1341.95,3862.49 1343.95,3868.49 ; 1343.95,3868.49 1343.95,3879.49 ; 1343.95,3868.49 1347.45,3873.99 ; 1343.95,3879.49 1347.45,3873.99 ; 1344.93,3748.01 U1001.AG6@1392.18,3748.01 ; 1344.93,3748.01 U1001.AG6@1392.18,3748.01 ; U1001.AG6@1392.18,3748.01 U1001.AH6@1407.93,3748.01 U1001.AJ6@1423.68,3748.01 U1001.AJ5@1423.68,3732.26 ; U1001.AG6@1392.18,3748.01 v4(1392.18,3763.76) ; U1001.AG6@1392.18,3748.01 v4(1392.18,3763.76) ; v4(1392.18,3763.76) U1001.AG8@1392.18,3779.51 ; U1001.AJ3@1423.68,3700.77 U1001.AJ4@1423.68,3716.51 U1001.AJ5@1423.68,3732.26 ; U3701.H8@1831.94,4463.72 v4(1831.94,4479.47) ; U3701.H8@1831.94,4463.72 v4(1831.94,4479.47) ; U3701.H8@1831.94,4463.72 U3701.G8@1847.69,4463.72 ; U3701.H8@1831.94,4463.72 U3701.G8@1847.69,4463.72 ; v4(1831.94,4479.47) U3701.H6@1831.94,4495.22 ; v4(1831.94,4479.47) 1831.94,4487.34 ; v4(1831.94,4479.47) 1831.94,4487.34 ; 1831.94,4487.34 U3701.H6@1831.94,4495.22 ; 1831.94,4487.34 U3701.H6@1831.94,4495.22 1847.43,4495.21 ; U3701.H6@1831.94,4495.22 1831.94,4503.09 ; U3701.H6@1831.94,4495.22 1847.43,4495.21 ; U3701.H6@1831.94,4495.22 1831.94,4503.09 ; 1831.94,4503.09 v4(1831.94,4510.96) ; 1831.94,4503.09 v4(1831.94,4510.96) ; v4(1831.94,4510.96) U3701.H4@1831.94,4526.71 ; v4(1831.94,4510.96) U3701.G5@1847.69,4510.96 ; U3701.H4@1831.94,4526.71 U3701.H3@1831.94,4542.46 ; U3701.H4@1831.94,4526.71 U3701.H3@1831.94,4542.46 ; U3701.H4@1831.94,4526.71 U3701.G4@1847.69,4526.71 ; U3701.H4@1831.94,4526.71 U3701.G4@1847.69,4526.71 ; U3701.H3@1831.94,4542.46 U3701.G3@1847.69,4542.46 ; 1847.43,4495.21 1847.69,4495.48 ; 1847.69,4495.48 U3701.G5@1847.69,4510.96 ; 1847.69,4495.48 U3701.G5@1847.69,4510.96 ; U3701.G5@1847.69,4510.96 U3701.G4@1847.69,4526.71 ; U3701.G5@1847.69,4510.96 U3701.G4@1847.69,4526.71 ; U3701.G5@1847.69,4510.96 U3701.G4@1847.69,4526.71 ; U3701.G4@1847.69,4526.71 U3701.G3@1847.69,4542.46 ; U3701.G4@1847.69,4526.71 U3701.G3@1847.69,4542.46 ; U3701.G4@1847.69,4526.71 U3701.G3@1847.69,4542.46 ; U3701.G4@1847.69,4526.71 U3701.F4@1863.44,4526.71 ; U3701.G4@1847.69,4526.71 U3701.F4@1863.44,4526.71 ; U3701.G3@1847.69,4542.46 U3701.F3@1863.44,4542.46 ; U3701.F4@1863.44,4526.71 U3701.F3@1863.44,4542.46 ; U3701.F4@1863.44,4526.71 U3701.F3@1863.44,4542.46 ; U3701.F4@1863.44,4526.71 U3701.E4@1879.19,4526.71 ; U3701.F4@1863.44,4526.71 U3701.E4@1879.19,4526.71 ; U3701.F4@1863.44,4526.71 U3701.F3@1863.44,4542.46 ; U3701.F3@1863.44,4542.46 U3701.E3@1879.19,4542.46 ; U3701.E4@1879.19,4526.71 U3701.D4@1894.93,4526.71 ; U3701.E4@1879.19,4526.71 U3701.E3@1879.19,4542.46 ; U3701.E3@1879.19,4542.46 U3701.D3@1894.93,4542.46 ; U3701.E3@1879.19,4542.46 U3701.D3@1894.93,4542.46 ; U3701.E3@1879.19,4542.46 U3701.D3@1894.93,4542.46 ; U3101.K8@1879.41,3898.59 v4(1895.16,3898.59) v4(1910.9,3898.59) ; U3701.D8@1894.93,4463.72 U3701.D7@1894.93,4479.47 v4(1910.68,4479.47) ; U3701.D8@1894.93,4463.72 U3701.C8@1909.2,4463.72 ; U3701.D8@1894.93,4463.72 U3701.D7@1894.93,4479.47 v4(1910.68,4479.47) ; U3701.D8@1894.93,4463.72 U3701.C8@1909.2,4463.72 ; U3701.D4@1894.93,4526.71 U3701.C4@1907.92,4526.71 ; U3701.D4@1894.93,4526.71 U3701.D3@1894.93,4542.46 ; U3701.D4@1894.93,4526.71 U3701.C4@1907.92,4526.71 ; U3701.D3@1894.93,4542.46 v4(1910.68,4542.46) ; U3701.D3@1894.93,4542.46 v4(1910.68,4542.46) ; U3701.C4@1907.92,4526.71 1908.3,4527.09 U3701.C4@1909.49,4526.9 ; U3701.C8@1909.2,4463.72 1909.57,4464.09 U3701.C8@1910.68,4464.09 ; U3701.C4@1909.49,4526.9 v4(1910.68,4526.71) ; U3701.C4@1909.49,4526.9 v4(1910.68,4526.71) ; v4(1910.68,4447.97) v4(1926.43,4447.97) U3701.B8@1926.43,4462.95 ; v4(1910.68,4447.97) U3701.C8@1910.68,4463.72 ; v4(1910.68,4447.97) U3701.C8@1910.68,4463.72 ; U3701.C8@1910.68,4463.72 U3701.C8@1910.68,4464.09 ; U3701.C8@1910.68,4463.72 U3701.C8@1910.68,4464.09 ; U3701.C8@1910.68,4463.72 U3701.C8@1910.68,4464.09 ; U3701.C8@1910.68,4464.09 1910.68,4474.3 ; U3701.C8@1910.68,4464.09 1910.68,4471.69 ; U3701.C8@1910.68,4464.09 1910.68,4471.69 ; U3701.C8@1910.68,4464.09 U3701.B8@1925.3,4464.09 ; 1910.68,4471.69 1910.68,4474.3 ; 1910.68,4471.69 v4(1910.68,4479.47) ; 1910.68,4474.3 v4(1910.68,4479.47) ; v4(1910.68,4479.47) U3701.B7@1925.94,4479.46 ; v4(1910.68,4479.47) U3701.B7@1925.94,4479.46 ; v4(1910.68,4479.47) v4(1910.68,4495.22) ; v4(1910.68,4479.47) 1910.68,4484.71 ; v4(1910.68,4479.47) 1910.68,4487.34 ; 1910.68,4484.71 v4(1910.68,4495.22) ; 1910.68,4484.71 1910.68,4487.34 ; 1910.68,4487.34 v4(1910.68,4495.22) ; 1910.68,4487.34 v4(1910.68,4495.22) ; v4(1910.68,4495.22) v4(1926.43,4495.22) v4(1926.43,4479.47) U3701.B7@1925.94,4479.46 ; 1910.68,4503.09 v4(1910.68,4495.22) 1910.68,4503.09 ; 1910.68,4503.09 v4(1910.68,4510.96) ; 1910.68,4503.09 v4(1910.68,4510.96) ; v4(1910.68,4510.96) v4(1910.68,4526.71) ; v4(1910.68,4526.71) 1910.68,4534.63 ; 1910.68,4534.63 v4(1910.68,4542.46) ; 1910.68,4534.63 v4(1910.68,4542.46) ; v4(1910.9,3867.09) U3101.G10@1926.65,3867.09 U3101.G9@1926.65,3882.84 ; v4(1910.9,3898.59) U3101.G8@1926.65,3898.59 ; v4(1910.9,3898.59) U3101.H7@1910.9,3914.34 ; U3101.H7@1910.9,3914.34 U3101.G7@1926.65,3914.34 ; U3701.B8@1925.3,4464.09 U3701.B8@1925.81,4463.58 ; U3701.B8@1925.3,4464.09 1925.3,4463.07 U3701.B8@1925.81,4463.58 ; U3701.B8@1925.3,4464.09 U3701.B8@1926.06,4464.09 ; U3701.B8@1925.81,4463.58 U3701.B8@1926.19,4463.96 ; U3701.B8@1925.81,4463.58 U3701.B8@1926.19,4463.96 ; U3701.B8@1925.81,4463.58 1926.05,4463.34 U3701.B8@1926.43,4462.95 ; U3701.B8@1925.81,4463.58 U3701.B8@1926.35,4463.7 ; U3701.B8@1925.81,4463.58 U3701.B8@1926.35,4463.7 ; U3701.B7@1925.94,4479.46 U3701.B7@1926.31,4479.09 ; U3701.B7@1925.94,4479.46 v4(1926.43,4479.47) ; U3701.B8@1926.06,4464.09 1926.31,4464.09 v4(1926.43,4463.72) ; U3701.B8@1926.06,4464.09 U3701.B8@1926.19,4463.96 ; U3701.B8@1926.19,4463.96 U3701.B8@1926.34,4463.81 ; U3701.B8@1926.19,4463.96 U3701.B8@1926.34,4463.81 ; U3701.B8@1926.19,4463.96 U3701.B8@1926.34,4463.81 ; U3701.B8@1926.19,4463.96 U3701.B8@1926.34,4463.81 ; U3701.B8@1926.19,4463.96 U3701.B8@1926.34,4463.81 ; U3701.B7@1926.31,4479.09 U3701.B7@1926.43,4478.97 ; U3701.B7@1926.31,4479.09 v4(1926.43,4479.47) ; U3701.B7@1926.31,4479.09 v4(1926.43,4479.47) ; U3701.B8@1926.35,4463.71 v4(1926.43,4463.72) ; U3701.B8@1926.35,4463.71 v4(1926.43,4463.72) ; v4(1926.43,4463.72) v4(1926.43,4463.72) ; v4(1926.43,4463.72) v4(1926.43,4463.72) ; v4(1926.43,4463.72) U3701.B8@1926.43,4462.95 ; v4(1926.43,4463.72) v4(1926.43,4463.72) ; U3701.B8@1926.35,4463.72 v4(1926.43,4463.72) ; U3701.B8@1926.35,4463.72 U3701.B8@1926.34,4463.81 ; U3701.B8@1926.35,4463.72 v4(1926.43,4463.72) ; U3701.B8@1926.34,4463.81 v4(1926.43,4463.72) ; U3701.B8@1926.34,4463.81 v4(1926.43,4463.72) ; U3701.B8@1926.34,4463.81 v4(1926.43,4463.72) ; U3701.B8@1926.34,4463.81 v4(1926.43,4463.72) ; U3701.B8@1926.34,4463.81 v4(1926.43,4463.72) ; U3701.B8@1926.34,4463.81 v4(1926.43,4463.72) ; U3701.B8@1926.43,4462.95 v4(1926.43,4463.72) ; U3701.B8@1926.43,4462.95 v4(1926.43,4463.72) ; v4(1926.43,4463.72) U3701.B8@1926.43,4463.97 ; v4(1926.43,4463.72) U3701.B8@1926.43,4463.97 ; U3701.B8@1926.43,4463.97 U3701.B7@1926.43,4478.97 ; U3701.B7@1926.43,4478.97 v4(1926.43,4479.47) ; U3101.G9@1926.65,3882.84 U3101.G8@1926.65,3898.59 ; U3101.G9@1926.65,3882.84 v4(1942.4,3882.84) v4(1942.4,3867.09) U3101.E10@1958.15,3867.09 ; U3101.G8@1926.65,3898.59 v4(1942.4,3898.59) ; U3101.G8@1926.65,3898.59 U3101.G7@1926.65,3914.34 ; U3101.E6@1958.15,3930.09 U3101.E5@1958.15,3945.83 ; U3801.6@2062.53,4618.11 U3801.6@2063.06,4617.59 U3801.6@2062.53,4618.11 ; U3801.7@2063.06,4602.11 U3801.7@2063.06,4601.84 U3801.7@2063.06,4602.11 ; U3801.11@2077.08,4537.12 U3801.11@2078.81,4538.85 U3801.11@2077.08,4537.12 ; v1@2094.55,4532.94 U3801.12@2094.55,4538.85 v1@2094.55,4532.94 ; v4(1029.98,3811) 1029.98,3826.74 v4(1029.98,3811)
  Top w10: R4104.1@444.95,3972.49 447.29,3974.83 v1(448.95,3974.83) ; C4116.2@445.56,3909.39 446.19,3909.47 446.29,3909.48 v1(448.95,3909.83) ; C4116.2@446.19,3909.39 448.95,3909.39 468.95,3909.39 C4115.2@468.95,3909.49 ; R1106.2@447.81,3843.33 448.31,3843.83 v1(448.95,3843.83) ; v1(448.95,4043.49) 448.95,4053.49 C4102.2@449.95,4053.49 ; C4107.2@448.95,4077.49 448.95,4077.41 448.87,4077.41 453.02,4073.28 453.14,4073.15 452.86,4072.87 v1(452.57,4072.83) ; v5(619.31,4855.09) 619.08,4854.86 619.08,4779.07 655.37,4742.78 658.26,4742.78 677.2,4723.84 Q6302.2@677.2,4722.85 ; C6314.2@1336.95,4500.49 1368.17,4500.49 v1(1373.04,4505.36) ; 1362.08,3882.66 1362.08,4036.39 ; 1368.2,3826.75 1379.56,3815.39 ; R3102.2@1744.15,3741.09 1744.15,3800.14 1747.27,3803.26 v1(1747.97,3803.56) ; R3105.2@1763.15,3868.09 1763.15,3853.09 C3101.2@1773.15,3843.09 1773.15,3830.33 1773.15,3829.51 v1(1773.9,3828.76) ; R3306.2@2188.65,3380.59 2192.6,3380.59 2192.6,3366.48 2193.65,3366.48 v1(2197.6,3366.48) ; v1(2304.14,4067.12) 2313.65,4057.61 C3456.1@2313.65,4045.59
  Top w12: v1(190.95,4195.83) 190.95,4180 202.12,4168.83 U6302.15@222.88,4168.83 ; 195.69,1880.83 197.36,1880.83 ; 197.36,1912.83 197.36,1880.83 ; 198.36,1836.83 198.36,1837.19 v1(228.96,1837.19) ; v1(223.95,4226.83) v1@224.02,4226.9 ; v1(229.06,1882.65) 227.24,1880.83 197.36,1880.83 ; v1(279.25,4067.14) 287.12,4067.14 300.64,4080.66 300.64,4083.76 ; v1(499.95,3371.83) 500.42,3372.3 525.1,3347.62 527.56,3347.62 C2008.2@527.56,3348.09 ; v1(626.31,1874.09) v1(645.31,1874.09) ; C5125.2@636.95,1811.49 636.95,1838.49 C5126.2@638.95,1838.49 ; v1(740.08,2259.11) v1(740.08,2306.11) ; v1(759.31,2581.09) 747.31,2581.09 739.95,2573.72 739.95,2315.11 ; C2057.2@770.95,3262.49 C2031.2@770.95,3283.49 ; F5001.7@798.53,4613.7 v1(818.7,4613.7) 890.65,4613.7 891.04,4614.09 v1(967.31,4614.09) ; C2041.2@826.95,3363.49 833.09,3363.49 844.31,3352.26 844.31,3344.49 C2051.2@844.31,3340.85 ; R2003.1@843.95,3323.49 843.95,3333.72 844.31,3334.09 C2051.2@844.31,3340.85 ; C2051.2@847.95,3344.49 C2051.2@844.31,3340.85 ; C2030.2@896.95,3308.49 897.23,3308.2 897.09,3308.14 896.95,3308.09 C2047.2@918.31,3308.09 ; v1(909.04,4034.11) v1(956.83,4034.11) ; C5007.1@1060.08,4522.11 1060.08,4534.11 1069.46,4543.49 L5006.2@1081.95,4543.49 ; v1(1114.95,3035.83) v1(1126.95,3035.83) ; v1(1299.06,4595.6) v1@1300.11,4596.08 ; v1(1310.95,4587.57) v1@1314.71,4591.33 ; C6303.2@1338.95,4441.49 1371.31,4441.49 v1(1371.31,4441.23) ; v1(1506.31,4915.09) C6205.2@1553.31,4915.09 ; v1(1510.31,4945.09) 1552,4945.09 C6210.2@1553.31,4945.09 ; v1(1524.43,4962.97) 1529.54,4968.09 C6207.2@1553.31,4968.09 ; v1(1716.65,4143.59) 1741.38,4143.59 v1(1741.38,4149.63) 1741.38,4159.31 v1(1717.72,4159.31) ; v1(1738.95,4473.53) C3707.2@1738.95,4494.49 ; R3732.2@1758.95,4543.49 C3705.2@1758.95,4566.49 ; v1(1776.31,4349.09) C3702.2@1810.31,4349.09 ; R3703.1@1873.95,4389.49 1873.95,4368.42 R3701.1@1875.5,4368.42 ; C3272.2@1935.65,3400.59 C3263.2@1970.65,3400.59 ; C3915.2@1947.31,2715.56 v1(1965.31,2715.56) ; v1@224.02,4226.9 U6302.13@241.58,4226.9 v1@224.02,4226.9 ; 300.64,4083.76 U6302.4@300.64,4110.76 300.64,4083.76 ; 739.95,2315.11 739.95,2306.24 v1(740.08,2306.11) ; 739.95,2315.11 740.08,2314.98 v1(740.08,2306.11) ; v1@1300.11,4596.08 U6303.9@1300.11,4613.48 v1@1300.11,4596.08 ; v1@1314.71,4591.33 U6303.6@1341.94,4591.33 v1@1314.71,4591.33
